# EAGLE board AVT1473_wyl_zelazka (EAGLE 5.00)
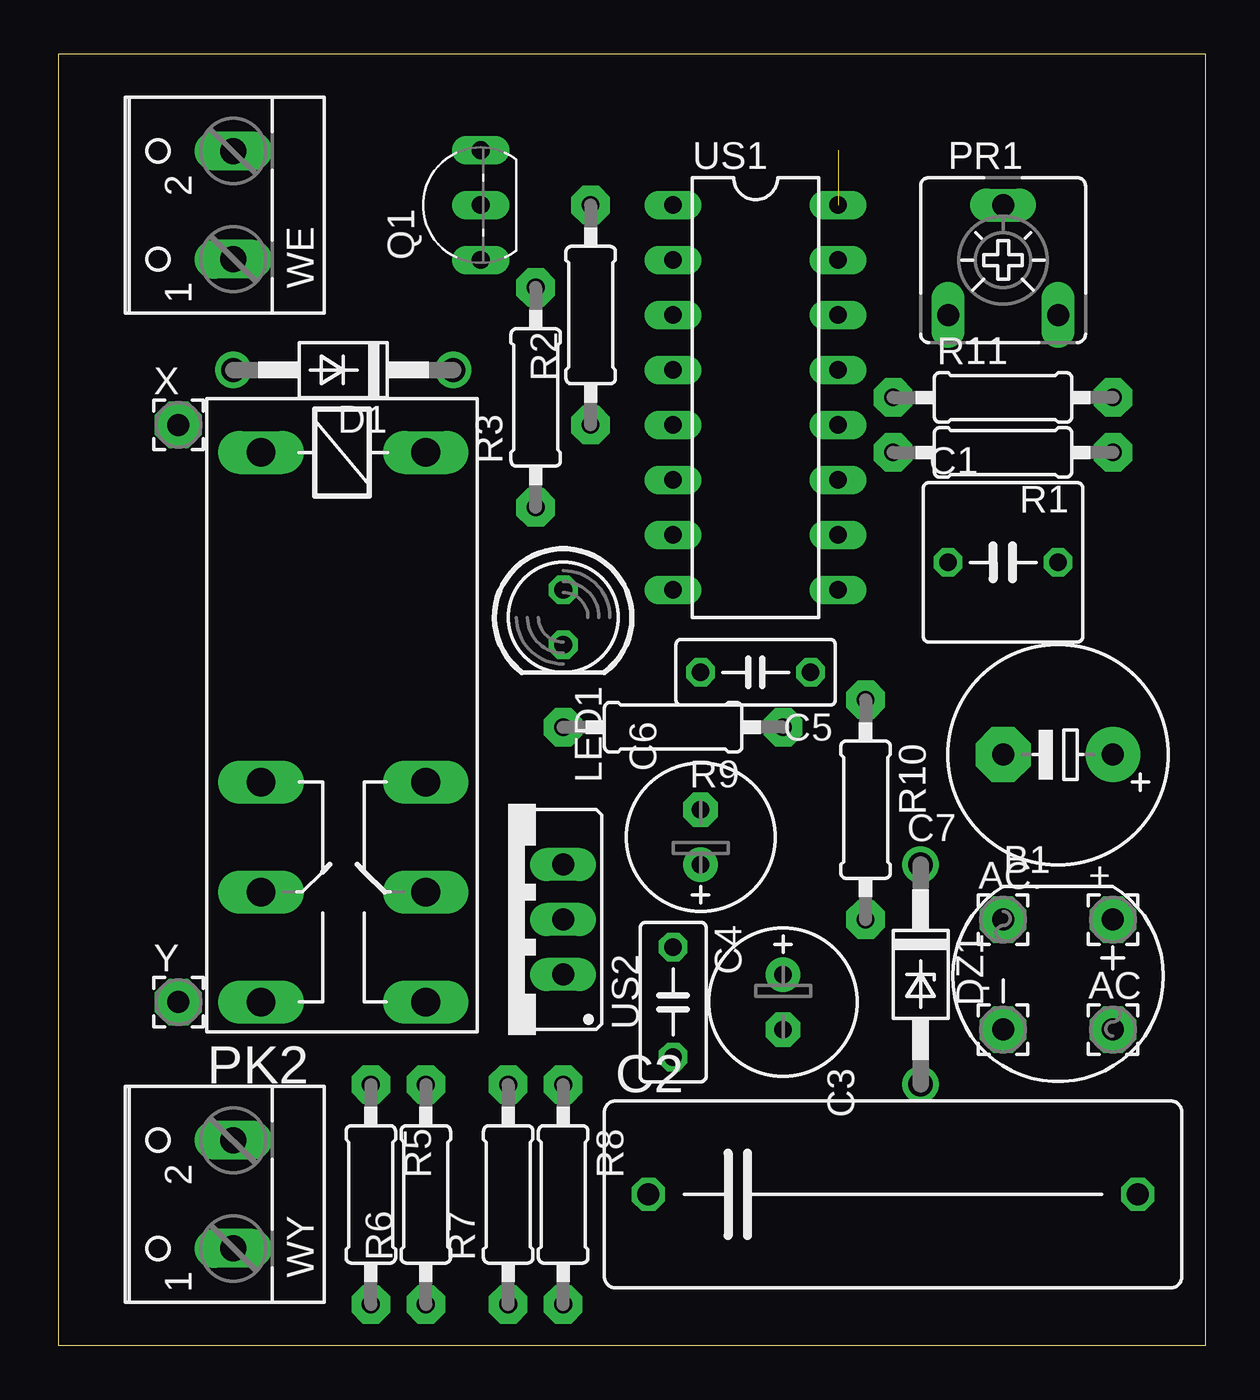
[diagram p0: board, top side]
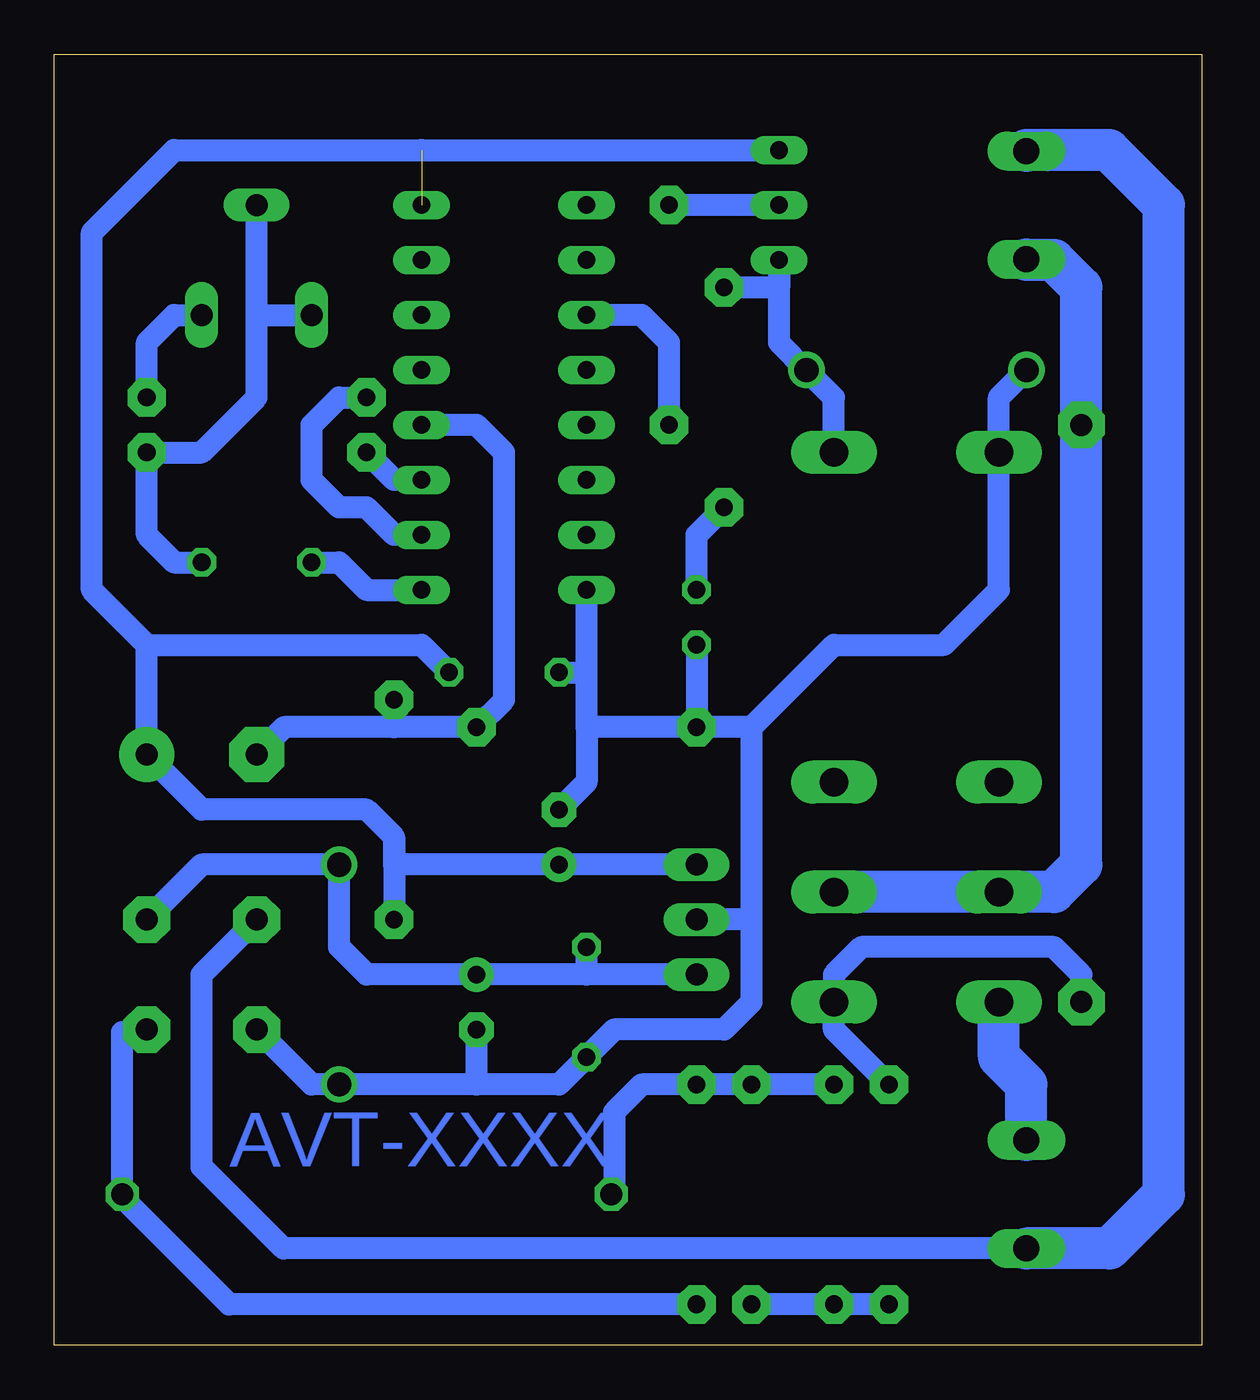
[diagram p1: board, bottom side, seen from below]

Size 53.01 x 59.68 mm. Coordinates in mm from the lower left corner, seen from the top.
Outline: 0,0 53.01,0 53.01,59.68 0,59.68 0,0
Copper layers (1*16): Top 0.035mm / dielectric 1.5mm / Bottom 0.035mm
Design rules "default": minimum track width 10mil, minimum drill 24mil, track to track 8mil, track to pad 8mil, pad to pad 8mil, via to via 8mil, smd to smd 8mil, copper to edge 40mil, drill to drill 8mil, minimum pad ring 10mil, minimum via ring 8mil, stop-mask expansion 4mil, vias tented up to drill 0mil, thermal gap 10mil

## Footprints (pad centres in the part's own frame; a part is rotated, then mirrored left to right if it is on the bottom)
2,15/1,0 = drill 1.016 pad 2.159 octagon: 1 0,0
RB1A = drill 1.016 round: + -2.54,2.54 | drill 1.016 octagon: - 2.54,-2.54; AC1 2.54,2.54; AC2 -2.54,-2.54
C050-075X075 = drill 0.813 octagon: 1 -2.54,0; 2 2.54,0
C225-087X268 = drill 1.016 octagon: 1 -11.303,0; 2 11.303,0
E2,5-7 = drill 0.813 pad 1.6 round: + -1.27,0 | drill 0.813 pad 1.6 octagon: - 1.27,0
C050-030X075 = drill 0.813 octagon: 1 -2.54,0; 2 2.54,0
E5-10,5 = drill 1.016 pad 2.54 round: + -2.54,0 | drill 1.016 pad 2.54 octagon: - 2.54,0
DO41-10 = drill 1.118 round: A 5.08,0; C -5.08,0
DO41Z10 = drill 1.118 round: A 5.08,0; C -5.08,0
LED5MM = drill 0.813 octagon: A -1.27,0; K 1.27,0
F4052 = drill 1.321 long: 1 -3.81,3.81; 2 -3.81,-3.81; O1 11.43,-3.81; O2 11.43,3.81; P1 16.51,-3.81; P2 16.51,3.81; S1 21.59,-3.81; S2 21.59,3.81
CA6V = drill 1.016 long: A -2.54,-2.54; E 2.54,-2.54; S 0,2.54
TO92-EBC = drill 0.813 long: B 0,-1.27; C -2.54,-1.27; E 2.54,-1.27
0207/10 = drill 0.813 pad 1.778 octagon: 1 -5.08,0; 2 5.08,0
DIL16 = drill 0.813 long: 1 -8.89,-3.81; 2 -6.35,-3.81; 3 -3.81,-3.81; 4 -1.27,-3.81; 5 1.27,-3.81; 6 3.81,-3.81; 7 6.35,-3.81; 8 8.89,-3.81; 9 8.89,3.81; 10 6.35,3.81; 11 3.81,3.81; 12 1.27,3.81; 13 -1.27,3.81; 14 -3.81,3.81; 15 -6.35,3.81; 16 -8.89,3.81
78XXS = drill 1.016 long: GND 0,-2.54; IN -2.54,-2.54; OUT 2.54,-2.54
W237-102 = drill 1.194 long: 1 -2.5,-1.27; 2 2.5,-1.27

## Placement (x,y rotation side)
+  [2,15/1,0]  48.73,19.68 0 top
-  [2,15/1,0]  43.65,14.6 0 top
AC  [2,15/1,0]  48.73,14.6 0 top
AC.  [2,15/1,0]  43.65,19.68 0 top
B1  [RB1A]  46.19,17.14 270 top
C1  [C050-075X075]  43.65,36.19 0 top
C2  [C225-087X268]  38.57,6.98 0 top
C3  [E2,5-7]  33.49,15.87 270 top
C4  [C050-030X075]  28.41,15.87 270 top
C5  [C050-030X075]  32.22,31.11 180 top
C6  [E2,5-7]  29.68,23.49 90 top
C7  [E5-10,5]  46.19,27.3 180 top
D1  1N4004  [DO41-10]  13.17,45.08 180 top
DZ1  [DO41Z10]  39.84,17.14 270 top
LED1  [LED5MM]  23.33,33.65 270 top
PK2  12V  [F4052]  13.17,37.46 270 top
PR1  [CA6V]  43.65,50.16 0 top
Q1  BC557  [TO92-EBC]  18.25,52.7 90 top
R1  [0207/10]  43.65,41.27 180 top
R2  [0207/10]  24.6,47.62 90 top
R3  [0207/10]  22.06,43.81 90 top
R5  [0207/10]  14.44,6.98 270 top
R6  [0207/10]  16.98,6.98 90 top
R7  [0207/10]  20.79,6.98 90 top
R8  [0207/10]  23.33,6.98 270 top
R9  [0207/10]  28.41,28.57 180 top
R10  [0207/10]  37.3,24.76 270 top
R11  [0207/10]  43.65,43.81 0 top
US1  4060N  [DIL16]  32.22,43.81 270 top
US2  [78XXS]  20.79,19.68 90 top
WE  [W237-102]  6.82,52.7 90 top
WY  [W237-102]  6.82,6.98 90 top
X  [2,15/1,0]  5.55,42.54 0 top
Y  [2,15/1,0]  5.55,15.87 0 top

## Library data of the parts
+ - AC AC. X Y = wirepad
B1 = rectifier
C1-C7 R1-R3 R5-R11 = rcl
D1 DZ1 = diode
LED1 = led
PK2 = relay
PR1 = pot
Q1 = transistor-pnp
US1 = 40xx
US2 = v-reg
WE WY = con-wago-500

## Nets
+5V: C5.1 C6.+ C7.+ Q1.E R10.2 US1.16 US2.OUT
GND: -.1 B1.- C3.- C4.2 C5.2 C6.- D1.A DZ1.A LED1.K PK2.2 R9.2 US1.8 US2.GND
N$1: R1.2 US1.11
N$2: PR1.E R11.2
N$3: C1.1 US1.9
N$4: C1.2 PR1.A PR1.S R1.1
N$5: Q1.B R2.2
N$6: R2.1 US1.3
N$7: D1.C PK2.1 Q1.C R3.2
N$8: AC..1 B1.AC2 WE.2 WY.1
N$9: LED1.A R3.1
N$10: R5.2 R6.1 R7.1
N$11: C2.1 R6.2 R7.2 R8.1
N$12: AC.1 B1.AC1 C2.2 R8.2
N$13: PK2.P1 PK2.P2 WE.1 X.1
N$14: PK2.S1 WY.2
N$15: +.1 B1.+ C3.+ C4.1 DZ1.C US2.IN
N$16: PK2.S2 R5.1 Y.1
N$17: C7.- R9.1 R10.1 US1.12
N$18: R11.1 US1.10

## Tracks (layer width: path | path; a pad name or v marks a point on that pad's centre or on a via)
+5V  (1 unrouted)
  Bottom 1.016: Q1.E 36.03,55.24 47.46,55.24 51.27,51.43 51.27,34.92 48.73,32.38 | C5.1 36.03,32.38 48.73,32.38 | US2.OUT C6.+ 37.3,22.22 37.3,23.49 | 48.73,32.38 C7.+ 46.19,24.76 38.57,24.76 37.3,23.49 | 37.3,23.49 R10.2
GND
  Bottom 1.016: -.1 41.11,12.06 DZ1.A 33.49,12.06 | 33.49,12.06 29.68,12.06 C4.2 27.14,14.6 22.06,14.6 20.79,15.87 20.79,19.68 | 33.49,12.06 C3.- | 20.79,19.68 US2.GND | 20.79,19.68 20.79,28.57 | 20.79,28.57 R9.2 | LED1.K R9.2 | 28.41,28.57 28.41,31.11 | 20.79,28.57 16.98,32.38 11.9,32.38 9.36,34.92 PK2.2 9.36,43.81 D1.A | C5.2 28.41,31.11 | C6.- 28.41,26.03 28.41,28.57 | R9.2 28.41,28.57 | 28.41,31.11 US1.8
N$1
  Bottom 1.016: US1.11 37.3,40 R1.2
N$2
  Bottom 1.016: R11.2 48.73,46.35 47.46,47.62 PR1.E
N$3
  Bottom 1.016: C1.1 39.84,36.19 38.57,34.92 US1.9
N$4
  Bottom 1.016: 43.65,47.62 43.65,43.81 46.19,41.27 R1.1 48.73,37.46 47.46,36.19 C1.2 | 43.65,47.62 PR1.S | 43.65,47.62 PR1.A
N$5
  Bottom 1.016: Q1.B R2.2
N$6
  Bottom 1.016: R2.1 24.6,46.35 25.87,47.62 US1.3
N$7
  Bottom 1.016: R3.2 19.52,48.89 Q1.C 19.52,46.35 D1.C 16.98,43.81 PK2.1
N$8
  Bottom 1.016: WY.1 42.42,4.48 46.19,8.25 46.19,17.14 AC..1
  Bottom 1.93: WY.1 4.24,4.48 1.74,6.98 1.74,52.7 4.28,55.24 8.09,55.24 WE.2
N$9
  Bottom 1.016: LED1.A 23.33,37.46 R3.1
N$10
  Bottom 1.016: R5.2 R6.1 R7.1
N$11
  Bottom 1.016: R6.2 R7.2 R8.1 25.87,12.06 27.14,10.79 27.14,6.98 C2.1
N$12
  Bottom 1.016: R8.2 44.92,1.9 50,6.98 C2.2 49.87,14.47 AC.1
N$13
  Bottom 1.93: PK2.P2 PK2.P1 6.82,20.95 5.55,22.22 X.1 5.55,48.89 6.82,50.16 8.09,50.16 WE.1
N$14
  Bottom 1.93: WY.2 8.09,12.06 9.36,13.33 PK2.S1
N$15
  Bottom 1.016: +.1 46.19,22.22 DZ1.C 39.84,18.41 38.57,17.14 28.41,17.14 | 28.41,17.14 C3.+ | 28.41,17.14 C4.1 | US2.IN 28.41,17.14
N$16
  Bottom 1.016: Y.1 5.55,17.14 6.82,18.41 15.71,18.41 16.98,17.14 PK2.S2 16.98,14.6 R5.1
N$17
  Bottom 1.016: US1.12 33.49,42.54 32.22,41.27 32.22,29.84 R9.1 37.3,28.57 | 37.3,28.57 42.38,28.57 C7.- | 37.3,28.57 R10.1
N$18
  Bottom 1.016: US1.10 37.3,37.46 38.57,38.73 39.84,38.73 41.11,40 41.11,42.54 39.84,43.81 R11.1

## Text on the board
Bottom: AVT-XXXX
